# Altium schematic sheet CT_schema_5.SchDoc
size 252 x 159 mm
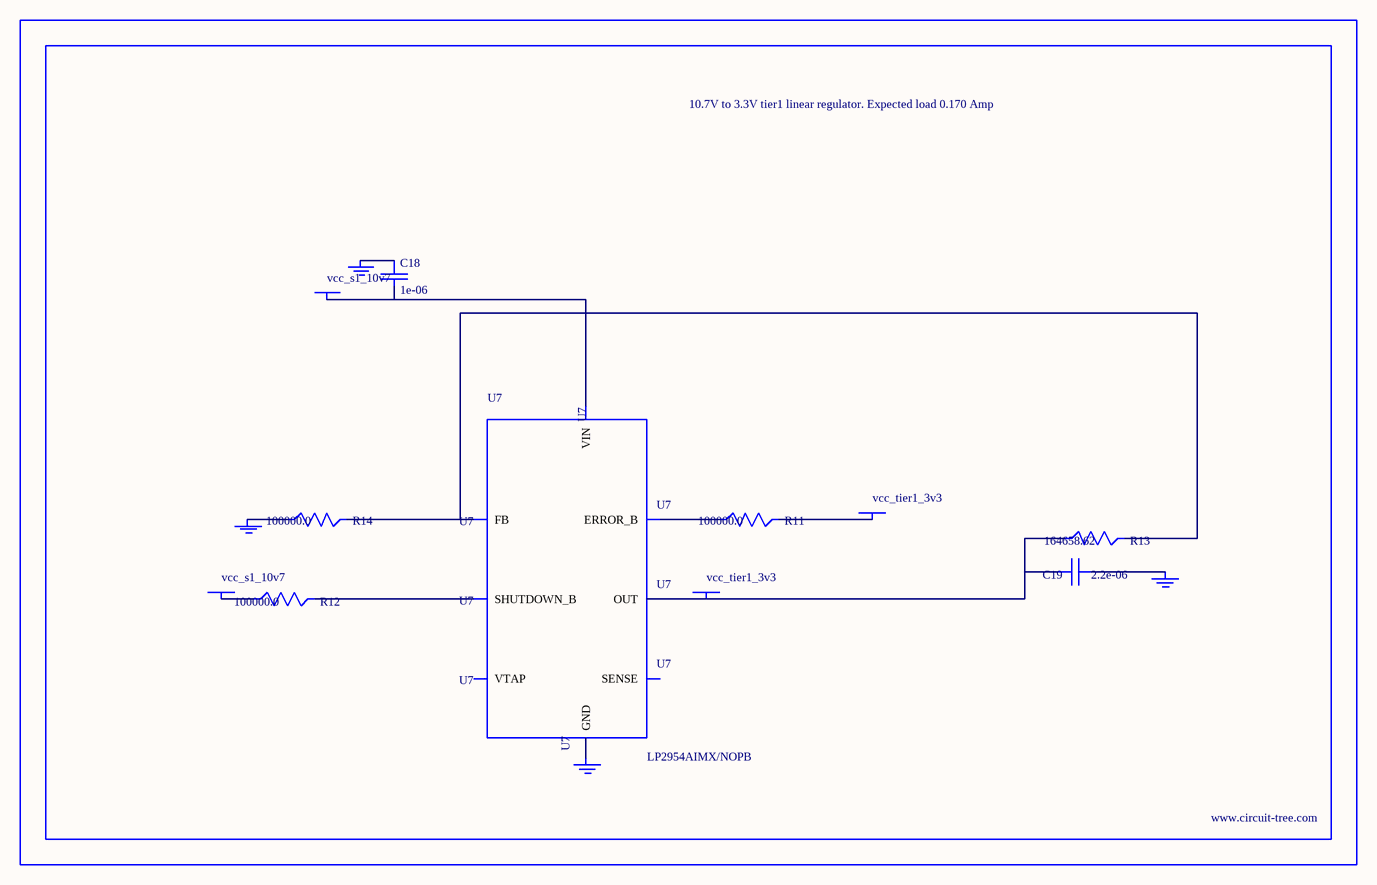
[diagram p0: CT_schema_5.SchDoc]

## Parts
BORDER4  (no value)
C18  1e-06  [EXV-9B]
C19  2.2e-06  [EXV-9B]
GND_INSTANCE_4_0  (no value)
GND_INSTANCE_4_1  (no value)
GND_INSTANCE_4_2  (no value)
GND_INSTANCE_4_3  (no value)
POWER_INSTANCE_4_0  vcc_s1_10v7
POWER_INSTANCE_4_1  vcc_tier1_3v3
POWER_INSTANCE_4_2  vcc_s1_10v7
POWER_INSTANCE_4_3  vcc_tier1_3v3
R11  100000.0  [R0603]
R12  100000.0  [R0603]
R13  164658.62  [R0603]
R14  100000.0  [R0603]
U7  LP2954AIMX/NOPB  [LP2954]

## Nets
NetC18_1: C18.1 GND_INSTANCE_4_2.0(GND)
NetC18_2: C18.2 POWER_INSTANCE_4_2.0(PWR) U7.8(VIN)
NetC19_1: C19.1 GND_INSTANCE_4_0.0(GND)
NetC19_2: C19.2 POWER_INSTANCE_4_3.0(PWR) R13.1 U7.1(OUT)
NetGND_INSTANCE_4_1_0: GND_INSTANCE_4_1.0(GND) R14.1
NetGND_INSTANCE_4_3_0: GND_INSTANCE_4_3.0(GND) U7.4(GND)
NetPOWER_INSTANCE_4_0_0: POWER_INSTANCE_4_0.0(PWR) R12.1
NetPOWER_INSTANCE_4_1_0: POWER_INSTANCE_4_1.0(PWR) R11.2
NetR11_1: R11.1 U7.5(ERROR_B)
NetR12_2: R12.2 U7.3(SHUTDOWN_B)
NetR13_2: R13.2 R14.2 U7.7(FB)

Not connected (* = marked no-connect by the designer): U7 2(SENSE) 6(VTAP)

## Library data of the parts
BORDER4 = BORDER_PAGE4
C18 = EDK105M050A9BAA
C19 = EDK225M050A9BAA
GND_INSTANCE_4_0-GND_INSTANCE_4_3 = GND
POWER_INSTANCE_4_0-POWER_INSTANCE_4_3 = PWR
R11 R12 R14 = RC0603JR-07100KL
R13 = R13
